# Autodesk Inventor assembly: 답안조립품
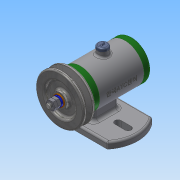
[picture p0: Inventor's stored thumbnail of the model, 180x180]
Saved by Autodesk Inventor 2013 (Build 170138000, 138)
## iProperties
Created: 2017-12
Part Number: 답안조립품
Document SubType Name: Assembly
Designer: Administrator
Author: Administrator
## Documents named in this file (14)
- C:\Users\Administrator\Desktop\471208V1010\답안조립품.iam
- C:\Users\Administrator\Desktop\471208V1010\V벨트풀리.ipt
- C:\Users\Administrator\Desktop\471208V1010\고무캡.ipt
- C:\Users\Administrator\Desktop\471208V1010\너트 M 8.ipt
- C:\Users\Administrator\Desktop\471208V1010\뒤커버.ipt
- C:\Users\Administrator\Desktop\471208V1010\베어링 15 x 32 x 9.ipt
- C:\Users\Administrator\Desktop\471208V1010\본체.ipt
- C:\Users\Administrator\Desktop\471208V1010\볼트 M4 x 12.ipt
- C:\Users\Administrator\Desktop\471208V1010\스프링와셔 8.ipt
- C:\Users\Administrator\Desktop\471208V1010\앞커버.ipt
- C:\Users\Administrator\Desktop\471208V1010\오일 실 15 25 7.ipt
- C:\Users\Administrator\Desktop\471208V1010\와셔 8x17.ipt
- C:\Users\Administrator\Desktop\471208V1010\축.ipt
- C:\Users\Administrator\Desktop\471208V1010\키 3 x 3 x 12.ipt
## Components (2 placed, 2 different names)
1. V벨트풀리:1
2. 고무캡:1
